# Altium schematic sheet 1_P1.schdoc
size 307 x 218 mm; Symbol: Drawing-Symbol_A4; Device: Drawing-Symbol_A4; @Project Name: ProbeMonkey; @Page Count: 1; @Update Date: 2026-01-30; @Create Date: 2026-01-29; @Schematic Name: Schematic1; @Page No: 1; @Page Name: P1; Company: EasyEDA.com; Version: V1.0; Page Size: A4; @Create Time: 22:36:52; @Update Time: 09:36:52; Width: 1170; Height: 825; Region Start: 1; X Region Count: 6; Y Region Count: 4; Blade Width: 10; Title Block Position: 3; @Board Name: Board1
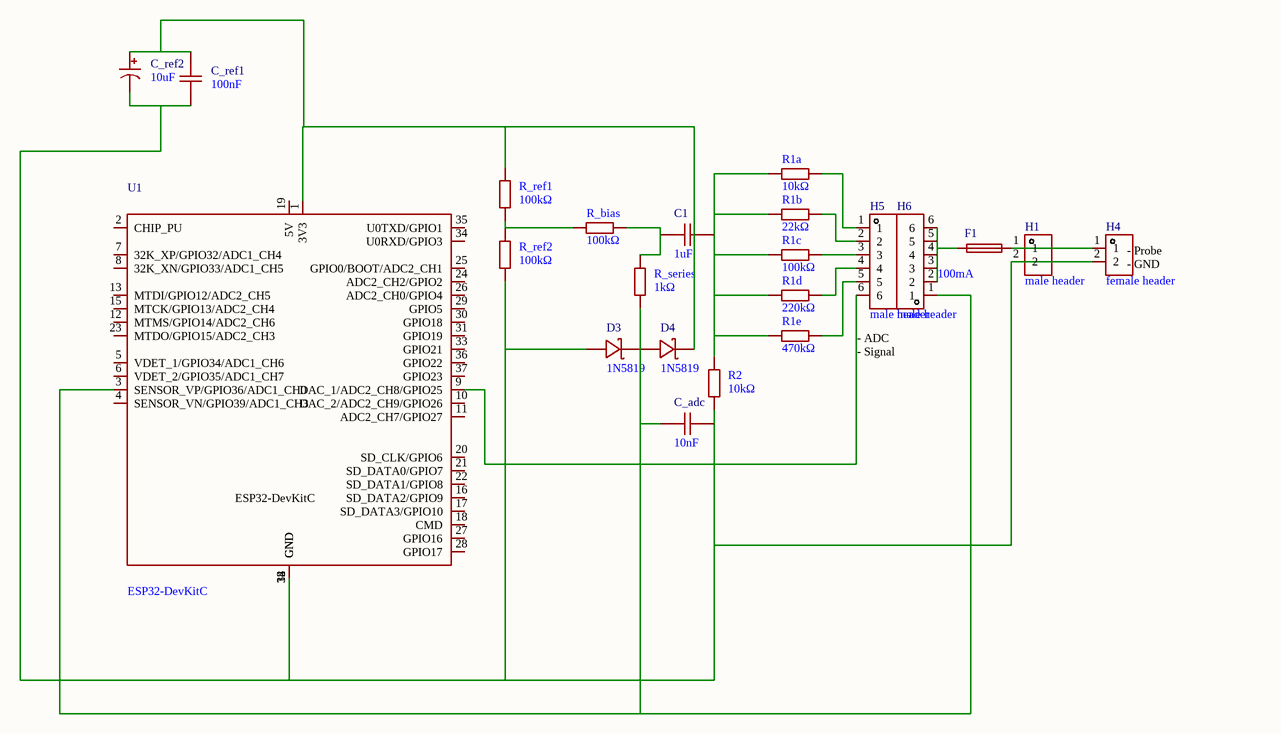
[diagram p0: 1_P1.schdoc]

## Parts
C1  1uF  [CAP-TH_L5.0-W3.2-P5.08-D0.6]
C_adc  10nF  [CAP-TH_L4.2-W3.8-P5.08-D0.6]
C_ref1  100nF  [CAP-TH_L4.2-W3.8-P2.54-D0.5]
C_ref2  10uF  [CAP-TH_BD4.0-P1.50-D0.8-FD]
D3  1N5819  [DO-41_BD2.4-L4.7-P8.70-D0.9-FD]
D4  1N5819  [DO-41_BD2.4-L4.7-P8.70-D0.9-FD]
F1  100mA  [FUSE-TH_L11.5-W4.8-P5.10-S1.9]
H1  male header  [HDR-TH_2P-P2.54-V-M]
H4  female header  [HDR-TH_2P-P2.54-V-M]
H5  male header  [HDR-TH_6P-P2.54-V-M]
H6  male header  [HDR-TH_6P-P2.54-V-M]
R1a  10kΩ  [RES-TH_BD2.3-L6.3-P10.30-D0.6]
R1b  22kΩ  [RES-TH_BD2.3-L6.3-P10.30-D0.6]
R1c  100kΩ  [RES-TH_BD2.3-L6.3-P10.30-D0.6]
R1d  220kΩ  [RES-TH_BD2.3-L6.3-P10.30-D0.6]
R1e  470kΩ  [RES-TH_BD2.3-L6.3-P10.30-D0.6]
R2  10kΩ  [RES-TH_BD2.3-L6.3-P10.30-D0.6]
R_bias  100kΩ  [RES-TH_BD2.3-L6.3-P10.30-D0.6]
R_ref1  100kΩ  [RES-TH_BD2.3-L6.3-P10.30-D0.6]
R_ref2  100kΩ  [RES-TH_BD2.3-L6.3-P10.30-D0.6]
R_series  1kΩ  [RES-TH_BD2.3-L6.3-P10.30-D0.6]
U1  ESP32-DevKitC  [ESP32-DevKitC]

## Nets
NetC1_1: C1.1 R_bias.1 R_series.1
NetC1_2: C1.2 R1a.2 R1b.2 R1c.2 R1d.2 R1e.2 R2.1
NetC_adc_1: C_adc.1 D3.2(K) D4.1(A) H6.1 R_series.2 U1.3(SENSOR_VP/GPIO36/ADC1_CH0)
NetC_adc_2: C_adc.2 C_ref1.1 C_ref2.2 D3.1(A) H1.2 H4.2 R2.2 R_ref2.1 U1.14(GND) U1.32(GND) U1.38(GND)
NetC_ref1_2: C_ref1.2 C_ref2.1 D4.2(K) R_ref1.2 U1.1(3V3)
NetF1_1: F1.1 H6.2 H6.3 H6.4 H6.5 H6.6
NetF1_2: F1.2 H1.1 H4.1
NetH5_1: H5.1 R1a.1
NetH5_2: H5.2 R1b.1
NetH5_3: H5.3 R1c.1
NetH5_4: H5.4 R1d.1
NetH5_5: H5.5 R1e.1
NetH5_6: H5.6 U1.9(DAC_1/ADC2_CH8/GPIO25)
NetR_bias_2: R_bias.2 R_ref1.1 R_ref2.2

Not connected (* = marked no-connect by the designer): U1 2(CHIP_PU) 4(SENSOR_VN/GPIO39/ADC1_CH3) 5(VDET_1/GPIO34/ADC1_CH6) 6(VDET_2/GPIO35/ADC1_CH7) 7(32K_XP/GPIO32/ADC1_CH4) 8(32K_XN/GPIO33/ADC1_CH5) 10(DAC_2/ADC2_CH9/GPIO26) 11(ADC2_CH7/GPIO27) 12(MTMS/GPIO14/ADC2_CH6) 13(MTDI/GPIO12/ADC2_CH5) 15(MTCK/GPIO13/ADC2_CH4) 16(SD_DATA2/GPIO9) 17(SD_DATA3/GPIO10) 18(CMD) 19(5V) 20(SD_CLK/GPIO6) 21(SD_DATA0/GPIO7) 22(SD_DATA1/GPIO8) 23(MTDO/GPIO15/ADC2_CH3) 24(ADC2_CH2/GPIO2) 25(GPIO0/BOOT/ADC2_CH1) 26(ADC2_CH0/GPIO4) 27(GPIO16) 28(GPIO17) 29(GPIO5) 30(GPIO18) 31(GPIO19) 33(GPIO21) 34(U0RXD/GPIO3) 35(U0TXD/GPIO1) 36(GPIO22) 37(GPIO23)

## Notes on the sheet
- (near H4) - Probe
  - GND
- - ADC
  - Signal

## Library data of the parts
C1 = CD1H105MC9BEF4E100: Manufacturer: Dersonic(德尔创); Add into BOM: yes; Tolerance: ±20%; Voltage Rating: 50V; Temperature Coefficient: Y5V; Pin Spacing: 5.08mm
C_adc = CD1H103KC94ER1D000: Manufacturer: Dersonic(德尔创); Add into BOM: yes; Tolerance: ±10%; Voltage Rating: 50V; Temperature Coefficient: X7R
C_ref1 = 178MU0011: Manufacturer: KNSCHA(科尼盛); Add into BOM: yes; Tolerance: ±20%; Voltage Rating: 50V; Temperature Coefficient: Y5V; Pin Spacing: 2.54mm
C_ref2 = KF106M025C05RR0VH2FP0: Manufacturer: Chengx(承兴); Symbol: 10uF 25V 4*5; Add into BOM: yes; Tolerance: ±20%; Voltage Rating: 25V; Ripple Current: 20mA@120Hz; Pin Spacing: 1.5mm; Lifetime: 1000hrs@105℃
D3 D4 = 1N5819_C2474: Manufacturer: MDD(辰达半导体); Add into BOM: yes; Voltage - Forward(Vf@If): 600mV@1A; Voltage - DC Reverse(Vr): 40V; Current - Rectified: 1A; Reverse Leakage Current (Ir): 500uA@40V; Operating Junction Temperature Range: -65℃~+150℃; Non-Repetitive Peak Forward Surge Current: 25A
F1 = FRV075-240F: Manufacturer: FUZETEC(富致); Add into BOM: yes; Voltage - Max: 240V; Current - Max: 7.5A; Hold Current: 750mA; Trip Current: 1.5A; Power Dissipation: 2.6W; Resistance - Initial (Ri) (Min): 320mΩ; Resistance - Post Trip (R1) (Max): 840mΩ; Time to Trip(Max): 18s
H1 H4 = HX PH254-01-02-Z-L11.5 male header connector: Manufacturer: hanxia(韩下); Add into BOM: yes; Pin Structure: 1x2P; Pitch: 2.54mm; Circluar Pins/Square Pins: Pin Header; Current Rating: 3A; Voltage Rating (Max): 1kV
H5 H6 = HX PH254-01-06-Z-L11.5 through hole header: Manufacturer: hanxia(韩下); Add into BOM: yes; Pin Structure: 1x6P; Pitch: 2.54mm; Circluar Pins/Square Pins: Pin Header; Current Rating: 3A; Voltage Rating (Max): 1kV
R1a R1b R1c R1d R1e R2 R_bias R_ref1 R_ref2 R_series = LR1F10K: Manufacturer: TE Connectivity(泰科电子); Symbol: Res; Add into BOM: yes; Tolerance: ±1%; Power(Watts): 600mW; Temperature Coefficient: ±50ppm/℃
U1 = ESP32-DevKitC: Add into BOM: yes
